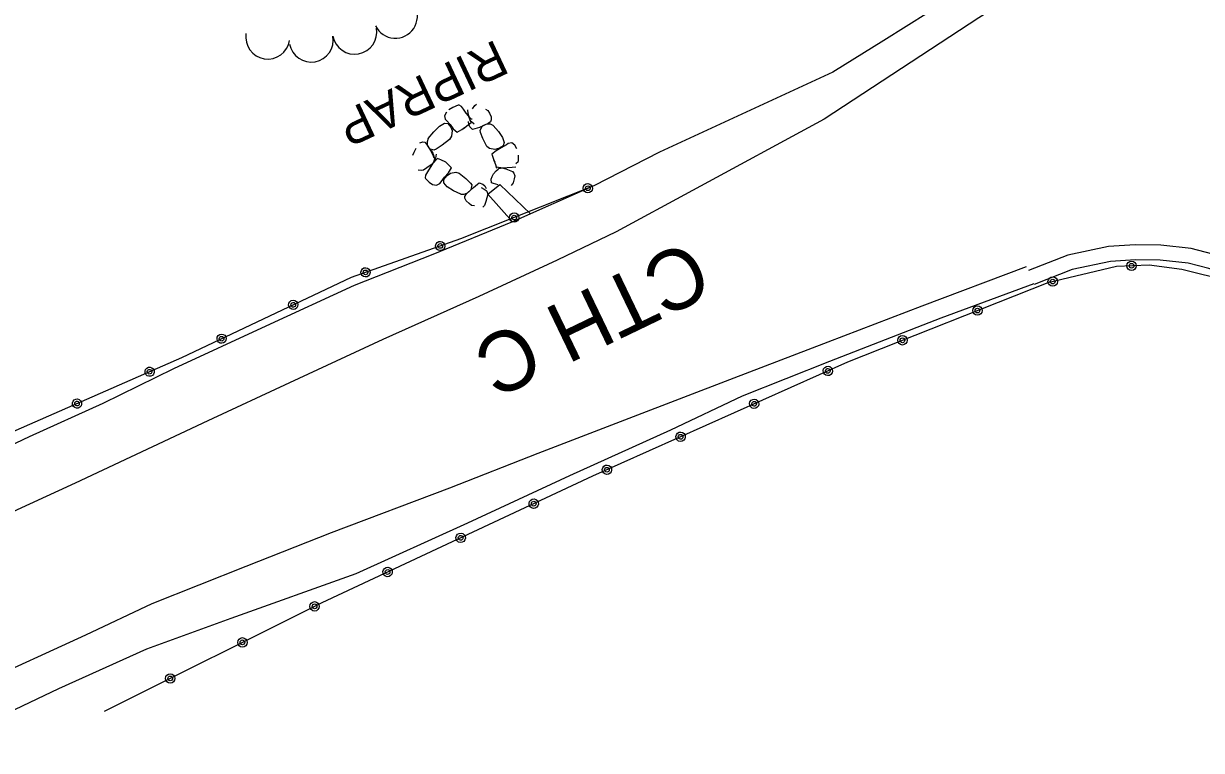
# Model space of a CAD drawing. Extents: x 588843 to 2552415, y 180129 to 269402.
# Drawn here: x 593585 to 593781.7, y 188103.3 to 188224.6 of the extents above; entities that cross this region are included whole.
import ezdxf

# ---------------------------------------------------------------- set-up
doc = ezdxf.new("R2010")
doc.units = 0
for name, color, linetype in [('E_BMGRD_P', 7, 'Continuous'), ('E_DRN_RipRap', 7, 'Continuous'), ('E_DRN_RipRap_Text', 7, 'Continuous'), ('E_LAND_TreeLine_P', 7, 'Continuous'), ('E_RDWY', 7, 'Continuous'), ('E_RDWY_C_and_G', 7, 'Continuous'), ('E_RDWY_Gravel', 7, 'Continuous'), ('E_RDWY_Text', 7, 'Continuous')]:
    doc.layers.add(name, color=color, linetype=linetype)

# ---------------------------------------------------------------- blocks, each defined once
blk = doc.blocks.new('RIPRT')
at = {"layer": 'E_DRN_RipRap_Text'}
blk.add_text('RIPRAP', height=12, dxfattribs=at).set_placement((-0.14, -3.59))

msp = doc.modelspace()

# ---------------------------------------------------------------- linework, layer by layer
at = {"layer": 'E_BMGRD_P'}
for points in [[(593680.23, 188197.49), (593657.94, 188188.64), (593639.66, 188182.2), (593611.38, 188168.81), (593577.3, 188153.88), (593546.19, 188140.94)], [(593830.31, 188022.68), (593827.22, 188056.44), (593824.93, 188080.28), (593822.5, 188101), (593819.35, 188125.14), (593817.13, 188142.84), (593816.03, 188150.15), (593813.88, 188155.97), (593811.34, 188161.06), (593806.13, 188167.89), (593801.08, 188172.64), (593794.93, 188177.37), (593791.65, 188179.34), (593786.25, 188181.59), (593778.38, 188183.53), (593772.93, 188184.24), (593767.45, 188184.05), (593756.03, 188181.32), (593722.56, 188168.08), (593680, 188149.05), (593634.79, 188127.93), (593598.42, 188109.8)]]:
    msp.add_lwpolyline(points, dxfattribs=at)
for centre, radius in [((593769.99, 188184.14), 0.784), ((593769.99, 188184.14), 0.395), ((593756.82, 188181.51), 0.784), ((593756.82, 188181.51), 0.395), ((593744.26, 188176.67), 0.784), ((593744.26, 188176.67), 0.395), ((593731.74, 188171.71), 0.784), ((593731.74, 188171.71), 0.395), ((593633.58, 188127.33), 0.784), ((593633.58, 188127.33), 0.395), ((593621.52, 188121.32), 0.784), ((593621.52, 188121.32), 0.395), ((593609.47, 188115.31), 0.784), ((593609.47, 188115.31), 0.395)]:
    msp.add_circle(centre, radius, dxfattribs=at)
for centre, major_axis, ratio in [((593679.21, 188197.08), (0.716, 0.284), 0.999969), ((593679.21, 188197.08), (0.361, 0.143), 0.999969), ((593666.91, 188192.2), (0.716, 0.284), 0.999969), ((593666.91, 188192.2), (0.361, 0.143), 0.999969), ((593654.56, 188187.45), (0.727, 0.256), 0.999969), ((593654.56, 188187.45), (0.366, 0.129), 0.999969), ((593642.08, 188183.05), (0.727, 0.256), 0.999969), ((593642.08, 188183.05), (0.366, 0.129), 0.999969), ((593630.02, 188177.63), (0.697, 0.33), 0.999969), ((593630.02, 188177.63), (0.351, 0.166), 0.999969), ((593618.06, 188171.98), (0.697, 0.33), 0.999969), ((593618.06, 188171.97), (0.351, 0.166), 0.999969), ((593606.03, 188166.47), (0.744, 0.2), 0.999968), ((593606.03, 188166.47), (0.375, 0.101), 0.999968), ((593719.28, 188166.61), (0.52, -0.587), 0.999994), ((593719.28, 188166.61), (0.262, -0.296), 0.999994), ((593593.91, 188161.16), (0.744, 0.2), 0.999968), ((593706.98, 188161.12), (0.52, -0.587), 0.999994), ((593593.91, 188161.16), (0.375, 0.101), 0.999968), ((593706.98, 188161.12), (0.262, -0.296), 0.999994), ((593694.69, 188155.62), (0.52, -0.587), 0.999994), ((593694.69, 188155.62), (0.262, -0.296), 0.999994), ((593682.39, 188150.12), (0.52, -0.587), 0.999994), ((593682.39, 188150.12), (0.262, -0.296), 0.999994), ((593670.17, 188144.46), (0.697, -0.36), 0.999999), ((593670.17, 188144.46), (0.351, -0.181), 0.999999), ((593657.97, 188138.76), (0.697, -0.36), 0.999999), ((593657.97, 188138.76), (0.351, -0.181), 0.999999), ((593645.77, 188133.06), (0.697, -0.36), 0.999999), ((593645.77, 188133.06), (0.351, -0.181), 0.999999)]:
    msp.add_ellipse(centre, major_axis=major_axis, ratio=ratio, dxfattribs=at)
at = {"layer": 'E_DRN_RipRap'}
for p, q in [((593660.31, 188210.89), (593660.63, 188211.09)), ((593655.59, 188209.78), (593655.25, 188209.18)), ((593655.25, 188209.18), (593655.36, 188208.6)), ((593656.68, 188210.55), (593656.02, 188210.17)), ((593657.55, 188210.92), (593656.68, 188210.55)), ((593657.7, 188210.93), (593657.55, 188210.92)), ((593658.1, 188210.73), (593657.7, 188210.93)), ((593658.44, 188210.27), (593658.1, 188210.73)), ((593658.91, 188209.63), (593658.44, 188210.27)), ((593659.3, 188209.14), (593658.91, 188209.63)), ((593659.22, 188209.57), (593659.14, 188210.17)), ((593659.39, 188208.98), (593659.22, 188209.57)), ((593659.73, 188208.07), (593659.3, 188209.14)), ((593659.94, 188210.31), (593660.31, 188210.89)), ((593662.11, 188210.3), (593662.53, 188210.04)), ((593662.53, 188210.04), (593662.77, 188209.6)), ((593662.77, 188209.6), (593663.04, 188208.98)), ((593653.48, 188206.51), (593654.44, 188207.44)), ((593654.44, 188207.44), (593655.28, 188207.93)), ((593655.28, 188207.93), (593655.85, 188207.89)), ((593655.36, 188208.6), (593655.61, 188208.37)), ((593655.61, 188208.37), (593656.21, 188207.7)), ((593655.85, 188207.89), (593656.35, 188207.28)), ((593656.21, 188207.7), (593656.73, 188206.99)), ((593656.35, 188207.28), (593656.55, 188206.69)), ((593658.17, 188206.9), (593658.62, 188207.22)), ((593658.46, 188207.03), (593659.21, 188207.66)), ((593659.21, 188207.66), (593659.73, 188208.07)), ((593659.36, 188207.72), (593659.29, 188208.22)), ((593659.5, 188207.3), (593659.36, 188207.72)), ((593659.74, 188208.61), (593659.39, 188208.98)), ((593659.76, 188208.15), (593659.47, 188208.51)), ((593659.96, 188206.86), (593659.5, 188207.3)), ((593659.91, 188208.58), (593659.74, 188208.61)), ((593660.22, 188207.75), (593659.76, 188208.15)), ((593661.12, 188207.24), (593660.33, 188206.97)), ((593662.57, 188207.88), (593661.12, 188207.24)), ((593661.21, 188206.76), (593661.64, 188207.48)), ((593662.35, 188207.79), (593661.64, 188207.48)), ((593662.94, 188207.78), (593662.35, 188207.79)), ((593662.97, 188208.18), (593662.57, 188207.88)), ((593663.42, 188207.57), (593662.94, 188207.78)), ((593663.08, 188208.49), (593662.97, 188208.18)), ((593663.04, 188208.98), (593663.08, 188208.49)), ((593663.42, 188207.57), (593664.31, 188206.56)), ((593652.54, 188205.37), (593652.36, 188204.84)), ((593652.54, 188205.37), (593653.48, 188206.51)), ((593656.11, 188205.24), (593654.86, 188204.27)), ((593656.43, 188205.77), (593656.11, 188205.24)), ((593656.55, 188206.69), (593656.43, 188205.77)), ((593656.73, 188206.99), (593657.37, 188206.42)), ((593657.37, 188206.42), (593658.17, 188206.9)), ((593660.33, 188206.97), (593659.96, 188206.86)), ((593661.29, 188206.38), (593661.21, 188206.76)), ((593661.69, 188205.36), (593661.29, 188206.38)), ((593662.33, 188204.07), (593661.69, 188205.36)), ((593664.31, 188206.56), (593664.98, 188205.55)), ((593664.98, 188205.55), (593665.24, 188204.7)), ((593650.18, 188203.11), (593650.52, 188203.76)), ((593651.16, 188204.63), (593651.65, 188204.8)), ((593651.65, 188204.8), (593651.96, 188204.77)), ((593651.96, 188204.77), (593652.29, 188204.46)), ((593652.29, 188204.46), (593653.03, 188203.2)), ((593652.36, 188204.84), (593652.4, 188204.27)), ((593652.4, 188204.27), (593652.75, 188203.65)), ((593653.51, 188203.42), (593652.75, 188203.65)), ((593653.03, 188203.2), (593653.36, 188202.5)), ((593653.05, 188203.36), (593653.31, 188202.94)), ((593653.87, 188203.6), (593653.51, 188203.42)), ((593654.86, 188204.27), (593653.87, 188203.6)), ((593662.77, 188203.71), (593662.33, 188204.07)), ((593663.66, 188203.54), (593662.77, 188203.71)), ((593663.91, 188203.33), (593663.17, 188202.75)), ((593664.31, 188203.69), (593663.66, 188203.54)), ((593664.76, 188203.8), (593663.91, 188203.33)), ((593665.05, 188204.13), (593664.31, 188203.69)), ((593665.6, 188204.33), (593664.76, 188203.8)), ((593665.24, 188204.7), (593665.05, 188204.13)), ((593665.89, 188204.56), (593665.6, 188204.33)), ((593666.5, 188204.63), (593665.89, 188204.56)), ((593667.01, 188204.26), (593666.5, 188204.63)), ((593667.36, 188203.66), (593667.01, 188204.26)), ((593649.97, 188202.61), (593650.18, 188203.11)), ((593653.36, 188201.32), (593652.86, 188200.87)), ((593654.11, 188202.07), (593653.24, 188201.15)), ((593653.31, 188202.94), (593653.5, 188202.41)), ((593653.36, 188202.5), (593653.49, 188202.17)), ((593653.6, 188201.81), (593653.36, 188201.32)), ((593653.5, 188202.41), (593653.58, 188201.98)), ((593653.77, 188202.11), (593653.51, 188201.7)), ((593653.58, 188201.98), (593653.6, 188201.81)), ((593653.86, 188202.78), (593653.77, 188202.11)), ((593654.66, 188201.8), (593654.11, 188202.07)), ((593655.48, 188201.44), (593654.66, 188201.8)), ((593655.85, 188201.11), (593655.48, 188201.44)), ((593663.17, 188202.75), (593663.45, 188201.93)), ((593663.45, 188201.93), (593663.65, 188201.46)), ((593663.48, 188201.89), (593663.78, 188201.02)), ((593667.2, 188201.22), (593667.57, 188201.54)), ((593667.57, 188201.54), (593667.62, 188201.68)), ((593667.62, 188201.68), (593667.63, 188202.59)), ((593651.37, 188200.04), (593650.87, 188200.12)), ((593651.74, 188200.11), (593651.37, 188200.04)), ((593652.33, 188200.5), (593651.74, 188200.11)), ((593652.12, 188199.29), (593652.06, 188198.84)), ((593652.45, 188199.83), (593652.12, 188199.29)), ((593652.86, 188200.87), (593652.33, 188200.5)), ((593652.9, 188200.56), (593652.45, 188199.83)), ((593653.24, 188201.15), (593652.9, 188200.56)), ((593655.29, 188198.95), (593655.93, 188199.68)), ((593655.69, 188199.22), (593656.25, 188199.59)), ((593656.43, 188200.48), (593655.85, 188201.11)), ((593655.93, 188199.68), (593656.43, 188200.48)), ((593656.25, 188199.59), (593657.18, 188199.76)), ((593657.18, 188199.76), (593657.74, 188199.61)), ((593657.74, 188199.61), (593658.84, 188198.69)), ((593663.23, 188199.04), (593663.48, 188199.49)), ((593663.48, 188199.49), (593663.87, 188199.97)), ((593663.78, 188201.02), (593663.95, 188200.42)), ((593663.87, 188199.97), (593664.22, 188200.28)), ((593663.92, 188200.66), (593665.09, 188200.49)), ((593664.22, 188200.28), (593664.36, 188200.4)), ((593664.36, 188200.4), (593664.9, 188200.49)), ((593664.9, 188200.49), (593665.5, 188200.34)), ((593665.09, 188200.49), (593665.75, 188200.56)), ((593665.5, 188200.34), (593666.05, 188200.12)), ((593665.75, 188200.56), (593666.59, 188200.62)), ((593666.05, 188200.12), (593666.64, 188199.88)), ((593666.59, 188200.62), (593667.19, 188200.67)), ((593666.64, 188199.88), (593666.85, 188199.61)), ((593666.85, 188199.61), (593666.99, 188199.16)), ((593652.06, 188198.84), (593652.11, 188198.71)), ((593652.11, 188198.71), (593652.73, 188198.11)), ((593652.73, 188198.11), (593653.29, 188197.71)), ((593653.29, 188197.71), (593653.93, 188197.57)), ((593653.93, 188197.57), (593654.49, 188197.85)), ((593654.49, 188197.85), (593654.69, 188198.16)), ((593654.69, 188198.16), (593655.29, 188198.95)), ((593655.14, 188198.55), (593655.69, 188199.22)), ((593655.17, 188197.97), (593655.14, 188198.55)), ((593655.74, 188197.31), (593655.17, 188197.97)), ((593656.77, 188196.66), (593655.74, 188197.31)), ((593658.84, 188198.69), (593659.61, 188197.93)), ((593659.61, 188197.93), (593659.83, 188197.63)), ((593659.83, 188197.63), (593659.69, 188196.82)), ((593660.1, 188197.23), (593660.76, 188197.77)), ((593660.76, 188197.77), (593661.07, 188198)), ((593661.07, 188198), (593661.68, 188197.78)), ((593661.68, 188197.78), (593661.98, 188197.46)), ((593661.98, 188197.46), (593662.24, 188197.04)), ((593663.07, 188198.6), (593663.23, 188199.04)), ((593663.13, 188197.98), (593663.07, 188198.6)), ((593663.46, 188197.86), (593663.13, 188197.98)), ((593664.21, 188197.63), (593663.46, 188197.86)), ((593666.71, 188197.98), (593666.42, 188197.55)), ((593666.9, 188198.65), (593666.71, 188197.98)), ((593666.99, 188199.16), (593666.9, 188198.65)), ((593658.01, 188196.09), (593656.77, 188196.66)), ((593658.01, 188196.09), (593658.55, 188196.08)), ((593658.55, 188196.08), (593659.12, 188196.29)), ((593658.67, 188195.71), (593658.95, 188196.13)), ((593658.68, 188195.4), (593658.67, 188195.71)), ((593658.9, 188194.97), (593658.68, 188195.4)), ((593658.95, 188196.13), (593660.1, 188197.23)), ((593659.12, 188196.29), (593659.69, 188196.82)), ((593661.38, 188197.18), (593661.89, 188196.94)), ((593661.89, 188196.94), (593662.23, 188196.7)), ((593662.36, 188195.46), (593662.17, 188194.86)), ((593662.23, 188196.7), (593662.36, 188196.59)), ((593662.36, 188196.59), (593662.48, 188196.09)), ((593662.48, 188196.09), (593662.36, 188195.46)), ((593659.4, 188194.52), (593658.9, 188194.97)), ((593659.8, 188194.22), (593659.4, 188194.52)), ((593660.3, 188194.14), (593659.8, 188194.22)), ((593661.96, 188194.2), (593661.69, 188193.91)), ((593662.17, 188194.86), (593661.96, 188194.2))]:
    msp.add_line(p, q, dxfattribs=at)
at = {"layer": 'E_LAND_TreeLine_P'}
for centre, start, end in [((593647.07, 188225.79), 206.1033, 26.1033), ((593625.76, 188222.32), 170.9105, 350.9105), ((593640.27, 188223.12), 190.3381, 10.3381), ((593633.02, 188221.8), 190.3381, 10.3381)]:
    msp.add_arc(centre, 3.68, start, end, dxfattribs=at)
at = {"layer": 'E_RDWY'}
for points in [[(593781.81, 188249.58), (593772.97, 188243.5), (593759.22, 188234.87), (593744.51, 188225.53), (593718.69, 188208.61), (593696.67, 188196.71), (593683.94, 188189.82), (593674.11, 188185.09), (593660.98, 188179.03), (593644.95, 188171.84), (593629.38, 188164.64), (593615.73, 188158.3), (593593.59, 188147.89), (593578.29, 188140.85), (593559.08, 188131.9), (593545.01, 188125.41), (593528.77, 188117.84), (593516.57, 188112.18), (593503.02, 188105.97), (593489.08, 188099.32)], [(593666.65, 188191.49), (593662.48, 188196.09), (593664.52, 188197.72), (593669.63, 188192.81)], [(593752.41, 188183.99), (593734.97, 188177.43), (593719.28, 188171.39), (593702.83, 188165.13), (593686.75, 188158.96), (593670.84, 188152.85), (593656.08, 188147.04), (593636.34, 188139.62), (593622.08, 188133.98), (593606.39, 188127.73), (593595.33, 188122.53), (593577.3, 188114.27), (593561.3, 188106.87), (593544.26, 188098.91), (593532.83, 188093.48), (593517.78, 188086.56), (593501.59, 188079.01), (593482.3, 188070.07), (593468.08, 188063.45), (593447.19, 188053.78), (593431.08, 188046.3), (593414.72, 188038.83)]]:
    msp.add_lwpolyline(points, dxfattribs=at)
at = {"layer": 'E_RDWY_C_and_G'}
for points in [[(593819.92, 188147.9), (593818.47, 188153.3), (593816.09, 188159.76), (593812.75, 188165.29), (593808.96, 188169.94), (593804.39, 188174.46), (593799.5, 188178.38), (593793.92, 188181.96), (593788.19, 188184.59), (593783.57, 188186.09), (593779.93, 188187.04), (593774.89, 188187.6), (593770.58, 188187.64), (593766.14, 188187.35), (593759.33, 188185.94), (593752.8, 188183.34)], [(593817.5, 188147.25), (593816.08, 188152.55), (593813.82, 188158.67), (593810.7, 188163.85), (593807.11, 188168.26), (593802.72, 188172.6), (593798.04, 188176.35), (593792.72, 188179.77), (593787.28, 188182.26), (593782.87, 188183.69), (593779.47, 188184.57), (593774.74, 188185.1), (593770.65, 188185.14), (593766.47, 188184.87), (593760.05, 188183.54), (593753.72, 188181.02)]]:
    msp.add_lwpolyline(points, dxfattribs=at)
at = {"layer": 'E_RDWY_Gravel'}
for points in [[(593806.21, 188371.19), (593805.8, 188325.67), (593806.09, 188301.88), (593802.63, 188287.53), (593796.7, 188274.16), (593790.91, 188265.64), (593783.7, 188258.17), (593776.29, 188252.01), (593758.44, 188240.45), (593728.62, 188221.72), (593720.11, 188216.47), (593691.17, 188203.12), (593680.23, 188197.49)], [(593680.23, 188197.49), (593679.94, 188197.39), (593666.65, 188191.49), (593653.34, 188186.04), (593640.19, 188180.83), (593625.45, 188174.06), (593610.04, 188166.94), (593598.2, 188161.18), (593585.94, 188155.62), (593573.66, 188149.84), (593553.98, 188140.8), (593546.28, 188137.29), (593539.89, 188134.23), (593528.22, 188127.92), (593518.91, 188122.75), (593511.76, 188118.83), (593502.27, 188113.58), (593493.31, 188108.39), (593483.56, 188103.68), (593467.22, 188096.06), (593452.76, 188089.29), (593439.4, 188083.15), (593426.93, 188077.44), (593416.12, 188072.34)], [(593753.68, 188181.11), (593738.16, 188175.41), (593719.58, 188168.16), (593705, 188162.42), (593692.98, 188156.71), (593676.15, 188149.08), (593659.11, 188141.18), (593640.47, 188132.77), (593619.59, 188125.29), (593605.54, 188120.19), (593590.8, 188113.55), (593575, 188106.04), (593560.21, 188099.2), (593545.68, 188092.45), (593530.56, 188085.51), (593511.53, 188076.69), (593492.13, 188067.52), (593479.33, 188061.56), (593460.33, 188052.93), (593445.36, 188045.83), (593425.71, 188036.76), (593412.44, 188030.78), (593397.11, 188023.55), (593368.54, 188010.26)]]:
    msp.add_lwpolyline(points, dxfattribs=at)

# ---------------------------------------------------------------- block references
at = {"layer": 'E_DRN_RipRap_Text', "xscale": 0.49999999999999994, "yscale": 0.49999999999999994, "rotation": -154.79394034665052}
msp.add_blockref('RIPRT', (593664.56, 188220.31), dxfattribs=at)

# ---------------------------------------------------------------- texts
at = {"layer": 'E_RDWY_Text'}
msp.add_text('CTH C', height=10, rotation=205.7119, dxfattribs=at).set_placement((593696.24, 188188.62))

doc.saveas('drawing.dxf')
